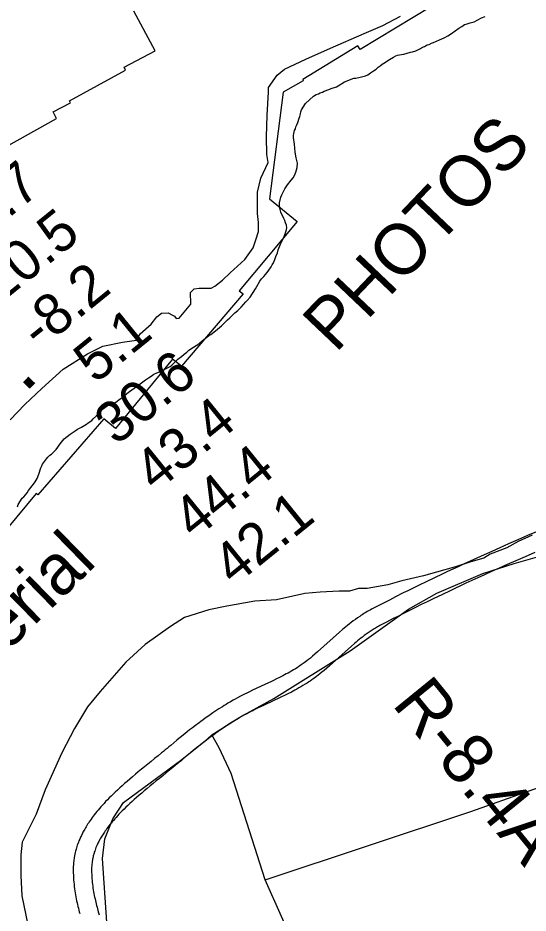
# Model space of a CAD drawing. Extents: x 3146026 to 3183936, y 897894 to 923344.
# Drawn here: x 3154340 to 3155173, y 918701 to 920164 of the extents above; entities that cross this region are included whole.
import ezdxf

# ---------------------------------------------------------------- set-up
doc = ezdxf.new("R2010")
doc.units = 0
for name, color, linetype in [('V-RIVR-EDGE', 7, 'Continuous'), ('V-RIVR-IDEN', 7, 'Continuous'), ('V-RIVR-RANG', 7, 'Continuous'), ('V-RIVR-RANG-IDEN', 7, 'Continuous'), ('V-ROAD-CNTR', 7, 'Continuous'), ('V-RRAP-RVMT', 7, 'Continuous'), ('V-RRAP-RVMT-IDEN', 7, 'Continuous'), ('V-SITE-VEGE', 7, 'Continuous'), ('V-TOPO-SHOR', 7, 'Continuous')]:
    doc.layers.add(name, color=color, linetype=linetype)

msp = doc.modelspace()

# ---------------------------------------------------------------- linework, layer by layer
at = {"layer": 'V-RIVR-EDGE'}
msp.add_lwpolyline([(3154326.7, 919506.8), (3154350.8, 919532.4), (3154378.9, 919558.5), (3154413.7, 919589.8), (3154453.3, 919615), (3154478.3, 919627.4), (3154510.3, 919634.3), (3154533.5, 919637.3), (3154539.6, 919647.6), (3154557.6, 919663.7), (3154566.5, 919675.3), (3154574.4, 919681.7), (3154585.4, 919681.9), (3154592.4, 919678.3), (3154595.4, 919676.7), (3154598.4, 919672.8), (3154603.3, 919673.1), (3154622.3, 919696.2), (3154622, 919702.9), (3154621.4, 919709), (3154621.7, 919715.3), (3154627.8, 919721.1), (3154635.7, 919722.3), (3154644.3, 919722.3), (3154651, 919722.3), (3154655.2, 919722.3), (3154661.6, 919725.6), (3154674.1, 919735.3), (3154686.7, 919747.5), (3154710.5, 919769), (3154723.9, 919788.5), (3154728.2, 919801.3), (3154732.5, 919814.7), (3154732.5, 919829.6), (3154731.1, 919844.2), (3154731.4, 919866.7), (3154731.4, 919879.2), (3154736.4, 919902.1), (3154748.3, 919927.9), (3154746.5, 919940.7), (3154746, 919969.7), (3154746.7, 920005.3), (3154749.2, 920043), (3154749.2, 920050.4), (3154763.3, 920070.7), (3154775.5, 920080.1), (3154810.3, 920096.5), (3154850.2, 920114.4), (3154905.4, 920138.6), (3154935.9, 920151.6), (3154964.8, 920167.1)], dxfattribs=at)
at = {"layer": 'V-ROAD-CNTR'}
for points in [[(3155189.6, 919325.3), (3155172.4, 919317.8), (3155156.3, 919310.8), (3155141.2, 919304.1), (3155127, 919297.8), (3155113.8, 919291.9), (3155101.4, 919286.3), (3155089.8, 919281.1), (3155078.9, 919276.1), (3155068.7, 919271.5), (3155059.1, 919267), (3155050.2, 919262.9), (3155041.8, 919259), (3155034, 919255.3), (3155019.3, 919248.3), (3155006.5, 919242.2), (3154995.3, 919236.7), (3154985.5, 919231.9), (3154976.9, 919227.7), (3154969.4, 919224), (3154956.4, 919217.5), (3154946.6, 919212.5), (3154939.3, 919208.7), (3154928.3, 919203.1), (3154917.3, 919197.3), (3154915, 919196.1), (3154912.7, 919194.8), (3154910.5, 919193.5), (3154908.3, 919192.3), (3154906.2, 919191), (3154904.1, 919189.7), (3154902.1, 919188.4), (3154900.2, 919187.1), (3154898.2, 919185.8), (3154894.5, 919183.3), (3154891, 919180.8), (3154887.6, 919178.2), (3154884.4, 919175.8), (3154881.3, 919173.4), (3154878.3, 919171), (3154875.5, 919168.7), (3154872.8, 919166.4), (3154870.1, 919164.2), (3154865.1, 919159.8), (3154829.2, 919127.6), (3154824.8, 919123.8), (3154820.9, 919120.5), (3154817.5, 919117.7), (3154814.5, 919115.3), (3154811.9, 919113.3), (3154809.6, 919111.5), (3154807.6, 919110), (3154805.8, 919108.7), (3154802.7, 919106.5), (3154800.3, 919104.8), (3154798.6, 919103.7), (3154795.9, 919101.9), (3154793.1, 919100.2), (3154790, 919098.3), (3154787, 919096.5), (3154784, 919094.8), (3154781, 919093.1), (3154778.2, 919091.6), (3154775.4, 919090.1), (3154772.7, 919088.7), (3154767.3, 919085.9), (3154762.2, 919083.4), (3154757.4, 919081.1), (3154752.9, 919078.9), (3154744.3, 919074.8), (3154729, 919067.7), (3154723.2, 919064.9), (3154718.2, 919062.5)], [(3155184.4, 919290.4), (3155168.3, 919283.3), (3155153.3, 919276.7), (3155139.2, 919270.4), (3155126, 919264.5), (3155113.7, 919259), (3155102.2, 919253.8), (3155091.3, 919248.8), (3155081.2, 919244.2), (3155071.7, 919239.8), (3155062.9, 919235.7), (3155054.6, 919231.8), (3155046.8, 919228.2), (3155032.2, 919221.2), (3155019.5, 919215.1), (3155008.4, 919209.8), (3154998.7, 919205), (3154990.2, 919200.8), (3154982.8, 919197.2), (3154969.9, 919190.7), (3154960.2, 919185.8), (3154953, 919182.1), (3154942.1, 919176.5), (3154931.3, 919170.8), (3154929.3, 919169.7), (3154927.4, 919168.7), (3154925.5, 919167.6), (3154923.7, 919166.5), (3154921.9, 919165.4), (3154920.1, 919164.3), (3154918.4, 919163.2), (3154916.7, 919162.1), (3154915.1, 919161), (3154911.8, 919158.7), (3154908.6, 919156.5), (3154905.6, 919154.3), (3154902.7, 919152), (3154899.9, 919149.9), (3154897.2, 919147.7), (3154894.6, 919145.5), (3154892.1, 919143.4), (3154889.6, 919141.4), (3154884.9, 919137.3), (3154849, 919105.1), (3154844.3, 919101), (3154840.1, 919097.5), (3154836.4, 919094.5), (3154833.2, 919091.8), (3154830.3, 919089.6), (3154827.7, 919087.6), (3154825.4, 919085.9), (3154823.4, 919084.4), (3154819.9, 919081.9), (3154817.2, 919080.1), (3154815.1, 919078.7), (3154812.1, 919076.6), (3154808.9, 919074.7), (3154805.4, 919072.6), (3154802.1, 919070.6), (3154798.8, 919068.7), (3154795.6, 919066.9), (3154792.4, 919065.2), (3154789.4, 919063.6), (3154786.5, 919062), (3154780.8, 919059.1), (3154775.5, 919056.5), (3154770.5, 919054), (3154765.8, 919051.8), (3154757, 919047.7), (3154741.8, 919040.5), (3154736.1, 919037.9), (3154731.2, 919035.5)], [(3154718.1, 919062.5), (3154713.7, 919060.3), (3154709.8, 919058.4), (3154706.4, 919056.7), (3154703.4, 919055.1), (3154698.3, 919052.4), (3154694.4, 919050.3), (3154691.5, 919048.7), (3154687.1, 919046.2), (3154682.9, 919043.6), (3154679.7, 919041.7), (3154676.7, 919039.8), (3154673.8, 919038), (3154668.2, 919034.5), (3154663.1, 919031.1), (3154658.3, 919027.9), (3154653.8, 919024.8), (3154649.7, 919021.9), (3154645.8, 919019.2), (3154642.2, 919016.6), (3154638.8, 919014.1), (3154635.7, 919011.8), (3154629.8, 919007.4), (3154624.7, 919003.5), (3154620.2, 919000.1), (3154616.4, 918997), (3154613, 918994.3), (3154607, 918989.6), (3154602.6, 918985.9), (3154599.3, 918983.2), (3154594.3, 918979), (3154589.3, 918974.9), (3154586.3, 918972.3), (3154583.3, 918969.8), (3154580.4, 918967.4), (3154577.4, 918965), (3154574.5, 918962.6), (3154568.7, 918957.8), (3154563, 918953.2), (3154557.4, 918948.7), (3154551.9, 918944.3), (3154546.6, 918939.9), (3154541.4, 918935.7), (3154536.4, 918931.6), (3154531.6, 918927.6), (3154526.9, 918923.6), (3154522.4, 918919.8), (3154518, 918916), (3154513.8, 918912.4), (3154509.8, 918908.8), (3154505.9, 918905.3), (3154502.2, 918901.8), (3154498.6, 918898.5), (3154495.2, 918895.2), (3154491.9, 918892), (3154488.8, 918888.9), (3154485.8, 918885.9), (3154483, 918882.9), (3154480.3, 918880), (3154477.7, 918877.2), (3154475.2, 918874.4), (3154472.9, 918871.7), (3154470.6, 918869), (3154468.5, 918866.5), (3154466.5, 918863.9), (3154464.5, 918861.5), (3154462.7, 918859.1), (3154461, 918856.7), (3154459.3, 918854.5), (3154457.7, 918852.2), (3154456.3, 918850.1), (3154454.8, 918847.9), (3154453.5, 918845.9), (3154452.2, 918843.9), (3154451, 918841.9), (3154449.9, 918840), (3154448.8, 918838.1), (3154447.8, 918836.3), (3154446.8, 918834.5), (3154445.9, 918832.8), (3154445, 918831.1), (3154443.4, 918827.8), (3154441.9, 918824.7), (3154440.6, 918821.8), (3154439.4, 918819), (3154438.4, 918816.4), (3154437.5, 918814)], [(3154731.3, 919035.5), (3154727, 919033.4), (3154723.3, 919031.6), (3154720.1, 919030), (3154717.3, 919028.5), (3154712.5, 919026), (3154708.9, 919024), (3154706.2, 919022.6), (3154702.3, 919020.3), (3154698.3, 919017.9), (3154695.4, 919016.2), (3154692.6, 919014.4), (3154689.8, 919012.7), (3154684.5, 919009.3), (3154679.6, 919006.1), (3154675.1, 919003), (3154670.8, 919000.1), (3154666.9, 918997.4), (3154663.2, 918994.8), (3154659.8, 918992.3), (3154656.5, 918989.9), (3154653.5, 918987.7), (3154647.9, 918983.5), (3154643, 918979.8), (3154638.7, 918976.4), (3154635, 918973.5), (3154631.7, 918970.9), (3154625.9, 918966.3), (3154621.6, 918962.8), (3154618.4, 918960.1), (3154613.5, 918956), (3154608.6, 918951.9), (3154605.6, 918949.3), (3154602.5, 918946.8), (3154599.5, 918944.3), (3154596.5, 918941.8), (3154593.5, 918939.3), (3154587.6, 918934.5), (3154581.8, 918929.9), (3154576.2, 918925.3), (3154570.8, 918920.9), (3154565.5, 918916.7), (3154560.4, 918912.5), (3154555.5, 918908.5), (3154550.8, 918904.5), (3154546.2, 918900.7), (3154541.9, 918897), (3154537.7, 918893.4), (3154533.6, 918889.9), (3154529.8, 918886.4), (3154526.1, 918883.1), (3154522.6, 918879.9), (3154519.3, 918876.7), (3154516.1, 918873.7), (3154513, 918870.7), (3154510.2, 918867.8), (3154507.4, 918865), (3154504.8, 918862.3), (3154502.3, 918859.6), (3154500, 918857.1), (3154497.8, 918854.6), (3154495.6, 918852.1), (3154493.6, 918849.8), (3154491.8, 918847.5), (3154490, 918845.3), (3154488.3, 918843.1), (3154486.7, 918841), (3154485.1, 918839), (3154483.7, 918837), (3154482.4, 918835.1), (3154481.1, 918833.2), (3154479.9, 918831.4), (3154478.7, 918829.7), (3154477.7, 918828), (3154476.7, 918826.3), (3154475.7, 918824.7), (3154474.8, 918823.2), (3154474, 918821.7), (3154473.2, 918820.2), (3154472.4, 918818.8), (3154471.7, 918817.5), (3154470.4, 918814.8), (3154469.2, 918812.3), (3154468.2, 918809.9), (3154467.2, 918807.7), (3154466.4, 918805.7), (3154465.7, 918803.6)], [(3154437.4, 918813.8), (3154436.7, 918811.6), (3154435.9, 918809.4), (3154435.3, 918807.3), (3154434.7, 918805.3), (3154434.2, 918803.4), (3154433.7, 918801.7), (3154433.3, 918800), (3154432.6, 918797), (3154432.1, 918794.2), (3154431.7, 918791.8), (3154431.3, 918789.7), (3154431.1, 918787.8), (3154430.9, 918786.1), (3154430.6, 918783.3), (3154430.4, 918781.1), (3154430.3, 918779.5), (3154430.1, 918777), (3154430.1, 918774.6), (3154430, 918770.5), (3154430.1, 918766.5), (3154430.2, 918762.6), (3154430.4, 918758.8), (3154430.6, 918755), (3154430.9, 918751.3), (3154431.3, 918747.7), (3154431.7, 918744.1), (3154432.2, 918740.6), (3154432.7, 918737.1), (3154433.2, 918733.7), (3154433.8, 918730.4), (3154434.3, 918727.1), (3154435, 918723.9), (3154435.6, 918720.7), (3154436.3, 918717.6), (3154437, 918714.5), (3154437.7, 918711.5), (3154438.4, 918708.5), (3154439.1, 918705.6), (3154439.9, 918702.8), (3154440.6, 918699.9)], [(3154465.8, 918803.9), (3154465.1, 918801.9), (3154464.5, 918800.2), (3154464, 918798.6), (3154463.6, 918797.1), (3154463.2, 918795.7), (3154462.8, 918794.3), (3154462.5, 918793.1), (3154462, 918790.7), (3154461.6, 918788.7), (3154461.3, 918786.9), (3154461, 918785.3), (3154460.8, 918783.9), (3154460.7, 918782.7), (3154460.4, 918780.5), (3154460.3, 918778.9), (3154460.2, 918777.7), (3154460.1, 918775.8), (3154460.1, 918774), (3154460, 918770.6), (3154460.1, 918767.2), (3154460.2, 918763.8), (3154460.3, 918760.5), (3154460.5, 918757.3), (3154460.8, 918754), (3154461.1, 918750.9), (3154461.5, 918747.7), (3154461.9, 918744.6), (3154462.3, 918741.6), (3154462.8, 918738.5), (3154463.3, 918735.6), (3154463.8, 918732.6), (3154464.4, 918729.7), (3154465, 918726.8), (3154465.6, 918724), (3154466.2, 918721.2), (3154466.9, 918718.5), (3154467.5, 918715.7), (3154468.2, 918713.1), (3154468.9, 918710.4), (3154469.6, 918707.8), (3154471, 918702.7), (3154472.5, 918697.6)]]:
    msp.add_lwpolyline(points, dxfattribs=at)
at = {"layer": 'V-RRAP-RVMT'}
for p, q in [((3155014.5, 920182.5), (3154898.7, 920112.3)), ((3154563.7, 920110.5), (3154529.3, 920175.1)), ((3154513.2, 920083.5), (3154563.7, 920110.5)), ((3154895.3, 920118.3), (3154805.1, 920063.2)), ((3154898.7, 920112.3), (3154895.3, 920118.3)), ((3154515.3, 920078.6), (3154513.2, 920083.5)), ((3154423.9, 920028.8), (3154515.3, 920078.6)), ((3154806, 920061.3), (3154772.8, 920042.6)), ((3154805.1, 920063.2), (3154806, 920061.3)), ((3154772.8, 920042.6), (3154750.5, 919868.3)), ((3154397.5, 920010.6), (3154425.5, 920025.3)), ((3154425.5, 920025.3), (3154423.9, 920028.8)), ((3154402.9, 919999.5), (3154397.5, 920010.6)), ((3154289.1, 919936.5), (3154402.9, 919999.5)), ((3154750.5, 919868.3), (3154795.7, 919831.1)), ((3154795.7, 919831.1), (3154701.1, 919718.1)), ((3154701.1, 919718.1), (3154707.9, 919712.9)), ((3154707.9, 919712.9), (3154606.9, 919594.7)), ((3154592.2, 919606.2), (3154499, 919493)), ((3154606.9, 919594.7), (3154592.2, 919606.2)), ((3154479.9, 919508.9), (3154372.3, 919384.4)), ((3154499, 919493), (3154479.9, 919508.9)), ((3154369.3, 919386.7), (3154288.1, 919288.8)), ((3154372.3, 919384.4), (3154369.3, 919386.7))]:
    msp.add_line(p, q, dxfattribs=at)
at = {"layer": 'V-SITE-VEGE'}
for points in [[(3154809.7, 920024.1), (3154822.8, 920036.3), (3154827.2, 920038.7), (3154830.9, 920040.2), (3154833.8, 920041.7), (3154837.2, 920042.9), (3154839.8, 920044.4), (3154847.9, 920047.3), (3154851.3, 920048.8), (3154860, 920051.5), (3154862.7, 920052.9), (3154873.4, 920059.5), (3154877.5, 920061.5), (3154884.3, 920064.2), (3154888.4, 920065.4), (3154891.6, 920065.4), (3154898.9, 920067.1), (3154907.4, 920069.6), (3154911.3, 920071.3), (3154915.9, 920074.2), (3154920.5, 920077.6), (3154925.1, 920080.5), (3154928.5, 920083.5), (3154931.7, 920085.7), (3154934.6, 920088.3), (3154937.5, 920090.1), (3154946.7, 920096.2), (3154953.5, 920099.8), (3154957.2, 920102), (3154960.1, 920103.2), (3154966.4, 920104.5), (3154970, 920105), (3154981.2, 920108.2), (3154984.6, 920108.9), (3154990, 920110.4), (3154997.5, 920114), (3155000.9, 920116.2), (3155003.8, 920117.4), (3155008.4, 920119.9), (3155011.6, 920120.9), (3155015.2, 920122.6), (3155018.6, 920123.8), (3155028.3, 920128.4), (3155035.9, 920131.6), (3155042.2, 920134.8), (3155048.3, 920138.5), (3155054.1, 920143.1), (3155059.9, 920147.2), (3155064.8, 920149.9), (3155069.4, 920153.1), (3155073.5, 920154.3), (3155078.4, 920156), (3155085.2, 920157.8), (3155097.1, 920164.1), (3155103.4, 920166.5)], [(3154471, 919516.6), (3154475.6, 919521.9), (3154478, 919524.4), (3154485.5, 919529.7), (3154499.4, 919536.1), (3154506.6, 919541.2), (3154509.3, 919542.9), (3154517.6, 919550), (3154521.7, 919553.2), (3154537, 919564.1), (3154541.6, 919567.8), (3154547.9, 919572.4), (3154553, 919575.9), (3154557.6, 919578.5), (3154561.8, 919581.5), (3154566.6, 919583.9), (3154571.2, 919585.6), (3154574.9, 919587.3), (3154581.7, 919591), (3154588.5, 919594.4), (3154591.4, 919596.6), (3154594.1, 919599), (3154601.1, 919606.1), (3154607.2, 919610.8), (3154611.5, 919614.4), (3154615.6, 919617.6), (3154619, 919621), (3154626.3, 919625.6), (3154635.1, 919631.5), (3154637.5, 919633.7), (3154640.4, 919635.6), (3154651.8, 919644.9), (3154654.7, 919646.6), (3154662.3, 919652.7), (3154665.9, 919655.4), (3154668.8, 919658.1), (3154672.2, 919660.7), (3154675.1, 919663.4), (3154682.2, 919670.5), (3154685.8, 919673.7), (3154690.9, 919678.8), (3154694.3, 919682), (3154698.9, 919685.9), (3154704.5, 919691.2), (3154712, 919699.7), (3154714.2, 919701.9), (3154719, 919707.5), (3154727.8, 919721.2), (3154729.9, 919725.3), (3154735, 919733.6), (3154737.9, 919737.5), (3154741.3, 919741.6), (3154744, 919744.6), (3154748.6, 919750.2), (3154753.4, 919757.2), (3154755.1, 919760.6), (3154757.1, 919763.8), (3154759.5, 919769.2), (3154761.2, 919774), (3154763.6, 919780.1), (3154764.8, 919785), (3154768.7, 919794), (3154774, 919805.2), (3154777.4, 919814.2), (3154778.6, 919818.1), (3154779.3, 919821.2), (3154778.3, 919825.4), (3154777.1, 919829.3), (3154775.6, 919833.1), (3154774.2, 919836.3), (3154769, 919846.3), (3154767.6, 919853.3), (3154767.3, 919857.4), (3154767.3, 919861.6), (3154769.5, 919871.3), (3154770.7, 919875), (3154776, 919884.9), (3154780.4, 919891.3), (3154786.4, 919898.8), (3154789.6, 919902.5), (3154791.8, 919906.6), (3154793.5, 919911.7), (3154795.9, 919919.5), (3154796.3, 919926.6), (3154794.4, 919935.6), (3154792.9, 919944.6), (3154791.6, 919957.7), (3154789.9, 919968.4), (3154790.2, 919971.8), (3154790.6, 919975.4), (3154791.6, 919979.8), (3154793, 919983), (3154794, 919985.9), (3154795.5, 919989.1), (3154797.2, 919993.4), (3154799.3, 920000), (3154800.1, 920003.2), (3154801.3, 920007.1), (3154802, 920010.7), (3154802.9, 920013.6), (3154809.7, 920024.1)], [(3154338.8, 919364.8), (3154340.2, 919368.7), (3154346.8, 919378.9), (3154349.2, 919381.3), (3154354.8, 919387.9), (3154357, 919391.3), (3154363, 919398.9), (3154365, 919402), (3154367.9, 919405.9), (3154369.3, 919408.6), (3154371, 919411.3), (3154373.9, 919418.1), (3154377.3, 919428.8), (3154378.5, 919431.7), (3154380, 919434.7), (3154386.3, 919443.2), (3154388.4, 919445.9), (3154391.8, 919449.3), (3154394.5, 919451.2), (3154399.1, 919455.1), (3154402, 919458.8), (3154408.6, 919468), (3154415.1, 919475.8), (3154424.8, 919483.6), (3154433.1, 919489.3), (3154437.2, 919491.9), (3154443.8, 919495.1), (3154451.5, 919500), (3154454.5, 919502.2), (3154460.3, 919506.1), (3154462.7, 919508.8), (3154467.8, 919513.4), (3154471, 919516.6)], [(3155180.1, 919318.5), (3155157.1, 919308.1), (3155138.3, 919297.7), (3155111.1, 919287.3), (3155100.7, 919281.1), (3155079.8, 919274.8), (3155054.7, 919266.5), (3155023.4, 919258.2), (3155002.5, 919252), (3154967, 919243.7), (3154944.1, 919237.5), (3154910.6, 919231.2), (3154896, 919231.3), (3154881.4, 919227.1), (3154864.7, 919227.1), (3154833.4, 919225.1), (3154808.3, 919223.1), (3154762.4, 919212.7)], [(3154762.4, 919212.7), (3154726.9, 919210.7), (3154681, 919202.4), (3154651.7, 919196.2), (3154612.1, 919183.7), (3154589.1, 919169.1), (3154547.3, 919140), (3154515.9, 919110.8), (3154474.1, 919062.8), (3154453.2, 919037.8), (3154432.2, 919002.4), (3154411.3, 918962.7), (3154384.1, 918902.2), (3154369.4, 918862.6), (3154346.4, 918816.7), (3154344.2, 918795.8), (3154344.2, 918762.4), (3154346.2, 918729), (3154369, 918618.4)]]:
    msp.add_lwpolyline(points, dxfattribs=at)
at = {"layer": 'V-TOPO-SHOR'}
for points in [[(3154488.1, 918637.8), (3154477.6, 918789.8), (3154481.5, 918822), (3154494.9, 918854.9), (3154512.2, 918881.5), (3154607.6, 918951.7), (3154649.1, 918984.9), (3154656.5, 918992), (3154702, 919021), (3154757.9, 919051.7), (3154882.6, 919129.5), (3154978, 919197.7), (3155024.4, 919223.5), (3155099.1, 919255.9), (3155150.4, 919272.2), (3155196.5, 919285.5)], [(3155196.5, 919285.5), (3155245.6, 919097.1), (3155261.7, 918999), (3155274.3, 918921.7), (3155317.1, 918731.4), (3155334.3, 918593.7), (3155332.5, 918527.2), (3155302.7, 918421.9), (3155251.8, 918304.8), (3155206.3, 918233.2), (3155156.7, 918165.9), (3155111.9, 918123.4), (3155071.4, 918085), (3155026.9, 918054.9), (3154943, 918263), (3154796.8, 918634.9), (3154743.8, 918754.8), (3155079.5, 918866.5), (3155270.4, 918934.3)], [(3154743.8, 918754.8), (3154688.1, 918928.8), (3154668.4, 918970.9), (3154656.5, 918992)]]:
    msp.add_lwpolyline(points, dxfattribs=at)

# ---------------------------------------------------------------- texts
at = {"layer": 'V-RIVR-IDEN'}
for s, rotation, p in [('PHOTOS', 46.432, (3154858.7, 919615)), ('Aerial', 44.3098, (3154267.6, 919073.8))]:
    msp.add_text(s, height=83, rotation=rotation, dxfattribs=at).set_placement(p)
at = {"layer": 'V-RIVR-RANG'}
for s, p in [('-40.7', (3154223, 919754.1)), ('-20.5', (3154286.2, 919676.5)), ('-8.2', (3154375.2, 919620)), ('5.1', (3154466, 919564.9)), ('30.6', (3154500.1, 919463.8)), ('43.4', (3154564.7, 919387.4)), ('44.4', (3154627.9, 919309.9)), ('42.1', (3154692.9, 919233.9))]:
    msp.add_text(s, height=67, rotation=39.0383, dxfattribs=at).set_placement(p)
at = {"layer": 'V-RIVR-RANG-IDEN'}
msp.add_text('R-8.4A', height=83, rotation=309.1819, dxfattribs=at).set_placement((3154949.4, 919042))
at = {"layer": 'V-RRAP-RVMT-IDEN'}
msp.add_text('REVET.', height=100, rotation=46.272, dxfattribs=at).set_placement((3154042.5, 919226.8))

doc.saveas('drawing.dxf')
